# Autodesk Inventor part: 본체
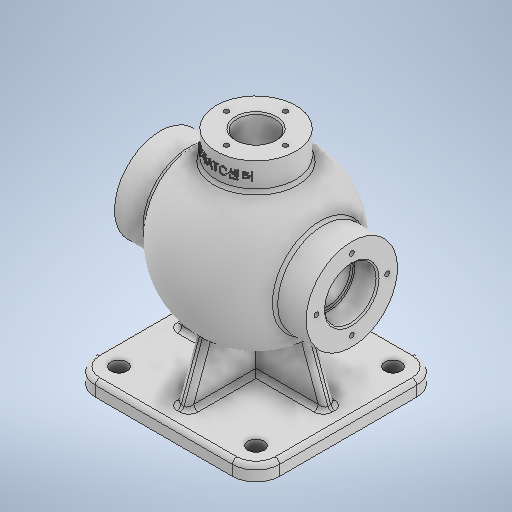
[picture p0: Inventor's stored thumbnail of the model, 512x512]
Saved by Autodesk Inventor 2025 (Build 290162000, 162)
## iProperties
Created: 2024-07
Part Number: 본체
Material: 일반
Document SubType Name: Modeling
Designer: Administrator
Density: 1 g/cm^3
Appearance: 기본값
Author: Administrator
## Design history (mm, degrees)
sketch "스케치1"
  geometry: L1 (62.5, 62.5)-(-62.5, 62.5); L2 (-62.5, 62.5)-(-62.5, -62.5); L3 (-62.5, -62.5)-(62.5, -62.5); L4 (62.5, -62.5)-(62.5, 62.5); L5 (62.5, 62.5)-(-62.5, -62.5); L6 (-62.5, 62.5)-(62.5, -62.5); 1 further point
  constraints: 12 end point, 2 midpoint, 2 parallel, 1 horizontal, 1 perpendicular
  dimensions: "d0" = 125 distance of L2.end L3.end; "d1" = 125 distance of L1.end L2.end
extrude "돌출1" new body sketch "스케치1" distance "d2" = 10; taper "d3" = 0 deg
sketch "스케치2"
  geometry: L1 (0, 62.5)-(0, -62.5) reference; L2 (139, 0)-(31, 0); A1 r 54 centre (85, 0) between (31, 0) and (139, 0); 3 further points
  constraints: 2 end point, 2 midpoint, 2 point on circle, 1 centre point, 1 horizontal, 1 horizontal alignment
  dimensions: "d5" = 54 radius of A1; "d6" = 85 distance of point (0, 0) A1.centre; "d7" = 108 distance of L2.start L2.end
revolve "회전1" sketch "스케치2" stored, may be unused: angle "d8" = 90 deg
sketch "스케치4"
  geometry: L1 (62.5, 10)-(-62.5, 10) reference; L2 (50.5, 10)-(35.236, 51.939); L3 (62.5, 0)-(62.5, 10) reference; L4 (0, 0)-(0, 46.413); L5 (-50.5, 10)-(-35.236, 51.939); L6 (-35.236, 51.939)-(35.236, 51.939); C1 r 54 at (0, 85) reference; 3 further points
  constraints: 8 end point, 2 symmetric about line, 1 horizontal, 1 point on line, 1 vertical
  dimensions: "d17" = 12 distance from line of L3 L2.start; "d18" = 20 deg angle of L3 L2
sketch "스케치3"
  geometry: L1 (129, 0)-(41, 0); C1 r 54 at (85, 0) reference; A1 r 44 centre (85, 0) between (41, 0) and (129, 0); 1 further point
  constraints: 2 end point, 2 point on circle, 1 centre point, 1 concentric, 1 horizontal
  dimensions: "d10" = 44 radius of A1; "d11" = 88 distance of L1.start L1.end
extrude "돌출2" join sketch "스케치4" stored distance "d19" = 8; taper "d20" = 0 deg
sketch "스케치5"
  geometry: L1 (10, -62.5)-(10, 62.5) reference; L2 (10, -50.5)-(58.644, -32.795); L3 (0, -62.5)-(10, -62.5) reference; L4 (0, 0)-(62.787, 0); L5 (10, 50.5)-(58.644, 32.795); L6 (58.644, 32.795)-(58.644, -32.795); 1 further point
  constraints: 8 end point, 2 symmetric about line, 1 horizontal, 1 point on line, 1 vertical
  dimensions: "d21" = 20 deg angle of L3 L2; "d22" = 12 distance from line of L3 L2.start
extrude "돌출3" join sketch "스케치5" stored distance "d23" = 8; taper "d24" = 0 deg
fillet "모깎기1" dims "d26" = 16
fillet "모깎기2" dims "d27" = 3
fillet "모깎기3" dims "d28" = 3
fillet "모깎기4" dims "d29" = 3
sketch "스케치6"
  geometry: C1 r 31 at (85, 0); A1 r 54 centre (85, 0) between (46.034, -37.385) and (46.034, 37.385) reference; 1 further point
  constraints: 1 centre point, 1 concentric
  dimensions: "d30" = 62 diameter of C1
extrude "돌출4" join sketch "스케치6" stored distance "d31" = 130; taper "d32" = 0 deg
sketch "스케치7"
  geometry: C1 r 31 at (0, 0) reference; 2 further points
  constraints: 1 coincident
hole "구멍1" sketch "스케치7" at (0, 0) diameter "d33" = 35; stored, may be unused: countersink angle "d37" = 90 deg, drill point angle "d39" = 0 deg; dims "d34" = 7.4, "d35" = 4, "d36" = 2, "d38" = 16
sketch "스케치8"
  geometry: C1 r 31 at (0, 0) reference; 2 further points
  constraints: 1 coincident
hole "구멍2" sketch "스케치8" at (0, 0) diameter "d40" = 35; stored, may be unused: countersink angle "d44" = 90 deg, drill point angle "d46" = 0 deg; dims "d41" = 6, "d42" = 4, "d43" = 2, "d45" = 16
sketch "스케치9"
  geometry: C1 r 17.5 at (0, 0) reference; 2 further points
  constraints: 1 coincident
hole "구멍3" sketch "스케치9" at (0, 0) diameter "d47" = 30; stored, may be unused: countersink angle "d51" = 90 deg, drill point angle "d53" = 0 deg; dims "d48" = 6, "d49" = 4, "d50" = 2, "d52" = 16
node "작업 평면1"
sketch "스케치10"
  geometry: C1 r 27 at (0, 0); 1 further point
  constraints: 1 centre point, 1 coincident
  dimensions: "d55" = 54 diameter of C1
extrude "돌출5" join sketch "스케치10" stored distance "d56" = 11; taper "d57" = 0 deg
revolve "회전4" stored, may be unused: angle "d58" = 90 deg
sketch "스케치11"
  geometry: A1 r 13 centre (46.5, -46.5) between (46.5, -59.5) and (59.5, -46.5) reference; 2 further points
  constraints: 1 coincident
hole "구멍4" sketch "스케치11" at (46.5, -46.5) diameter "d67" = 11; stored, may be unused: countersink angle "d71" = 90 deg, drill point angle "d73" = 0 deg; dims "d68" = 6, "d69" = 4, "d70" = 2, "d72" = 8
sketch "스케치12"
  geometry: A1 r 13 centre (46.5, 46.5) between (59.5, 46.5) and (46.5, 59.5) reference; 2 further points
  constraints: 1 coincident
hole "구멍5" sketch "스케치12" at (46.5, 46.5) diameter "d74" = 11; stored, may be unused: countersink angle "d78" = 90 deg, drill point angle "d80" = 0 deg; dims "d75" = 6, "d76" = 4, "d77" = 2, "d79" = 8
sketch "스케치13"
  geometry: A1 r 13 centre (-46.5, -46.5) between (-59.5, -46.5) and (-46.5, -59.5) reference; 2 further points
  constraints: 1 coincident
hole "구멍6" sketch "스케치13" at (-46.5, -46.5) diameter "d81" = 11; stored, may be unused: countersink angle "d85" = 90 deg, drill point angle "d87" = 0 deg; dims "d82" = 6, "d83" = 4, "d84" = 2, "d86" = 8
sketch "스케치14"
  geometry: A1 r 13 centre (-46.5, 46.5) between (-46.5, 59.5) and (-59.5, 46.5) reference; 2 further points
  constraints: 1 coincident
hole "구멍7" sketch "스케치14" at (-46.5, 46.5) diameter "d88" = 11; stored, may be unused: countersink angle "d92" = 90 deg, drill point angle "d94" = 0 deg; dims "d89" = 6, "d90" = 4, "d91" = 2, "d93" = 8
sketch "스케치15"
  geometry: C1 r 31 at (0, 0) reference; 2 further points
  constraints: 1 vertical alignment
  dimensions: "d95" = 24 distance of C1.centre point (0, 24)
hole "구멍8" sketch "스케치15" at (0, 24) diameter "d96" = 3.242; stored, may be unused: countersink angle "d100" = 90 deg, drill point angle "d102" = 120 deg; dims "d97" = 12, "d98" = 4, "d99" = 2, "d101" = 15
sketch "스케치16"
  geometry: C1 r 27 at (0, 0) reference; 2 further points
  constraints: 1 coincident
hole "구멍9" sketch "스케치16" at (0, 0) diameter "d106" = 26; stored, may be unused: countersink angle "d110" = 90 deg, drill point angle "d112" = 0 deg; dims "d107" = 12, "d108" = 4, "d109" = 2, "d111" = 40
sketch "스케치17"
  geometry: 2 further points
  constraints: 1 vertical alignment
  dimensions: "d113" = 20 distance of point (0, 0) point (0, 20)
hole "구멍10" sketch "스케치17" at (0, 20) diameter "d114" = 3.242; stored, may be unused: countersink angle "d118" = 90 deg, drill point angle "d120" = 120 deg; dims "d115" = 9, "d116" = 4, "d117" = 2, "d119" = 11
fillet "모깎기5" dims "d124" = 3
chamfer "모따기1" distance "d125" = 1; stored, may be unused: second distance "d126" = 2, angle "d127" = 45 deg
chamfer "모따기2" distance "d128" = 1; stored, may be unused: second distance "d129" = 2, angle "d130" = 45 deg
fillet "모깎기6" dims "d131" = 0.6
fillet "모깎기7" dims "d132" = 3
chamfer "모따기3" distance "d133" = 1; stored, may be unused: second distance "d134" = 2, angle "d135" = 45 deg
sketch "스케치18"
  geometry: L1 (27, 150)-(-27, 150) reference; 3 further points
  constraints: 1 coincident, 1 vertical alignment, 1 other
  dimensions: "d136" = 9 distance from line of L1 point (0, 141)
feature "엠보싱1" sketch "스케치18" dims "d10" = 44, "d11" = 88, "d137" = 0.5, "d138" = 0
node "솔리드1"
pattern_circular "원형 패턴1" dims angle "d104" = 360 deg
mirror "미러1"
pattern_circular "원형 패턴2" dims angle "d122" = 360 deg
feature "A9D066F2-1C7D-4E18-AEED-F7BC21143FA4" dims "d33" = 35, "d34" = 7.4, "d35" = 4, "d36" = 2, "d37" = 90 deg, "d38" = 16, "d39" = 0
other parameters: "d13" = 0.5, "d14" = 2, "d15" = 0, "d59" = 0.5, "d60" = 2, "d61" = 0, "d63" = 0.5, "d64" = 2, "d65" = 0
